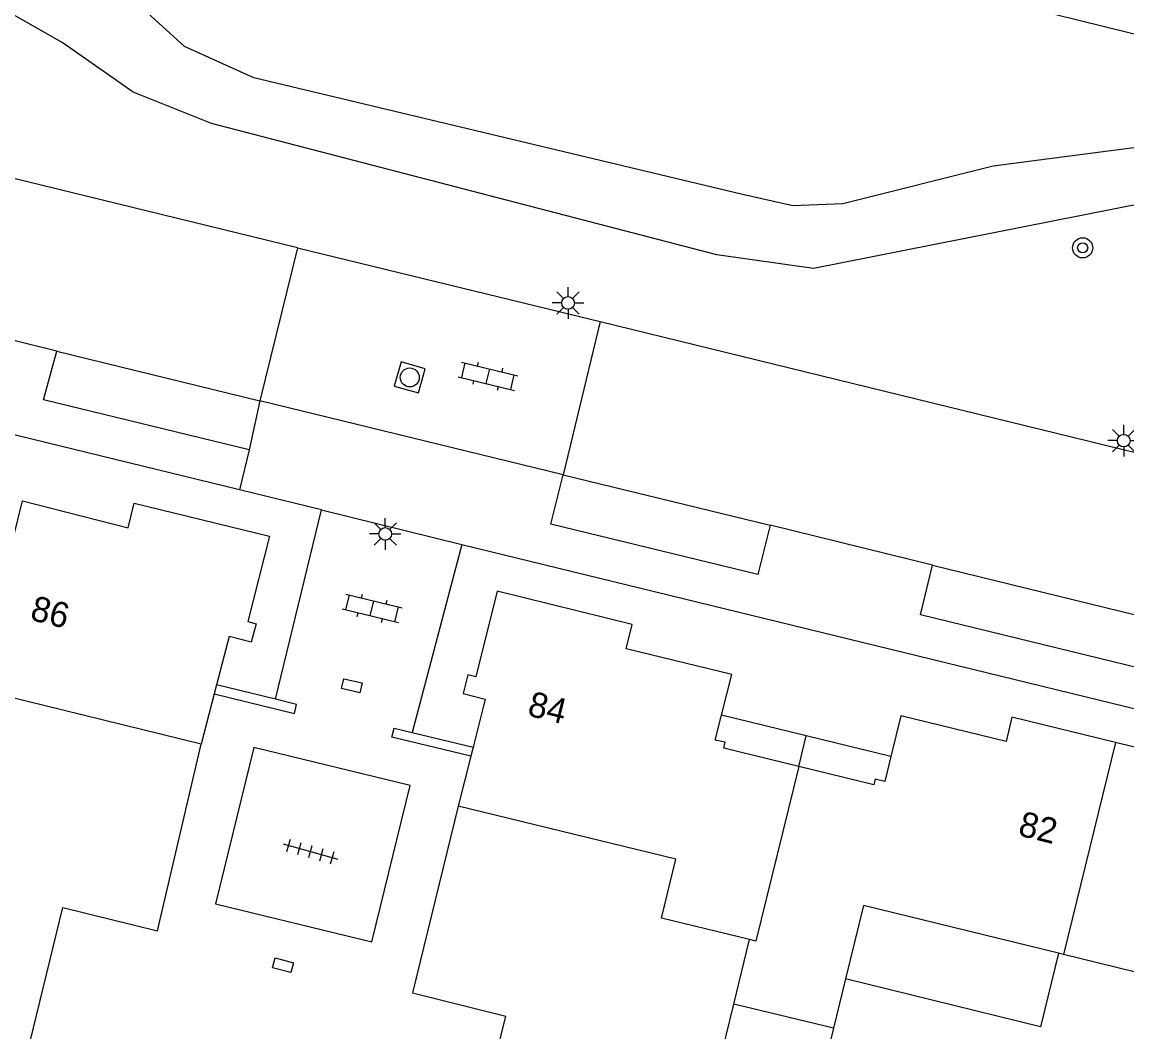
# Model space of a CAD drawing. Extents: x 125000 to 129004, y 397500 to 399008.
# Drawn here: x 126393.13 to 126436.93, y 398628.24 to 398668.28 of the extents above; entities that cross this region are included whole.
import ezdxf

# ---------------------------------------------------------------- set-up
doc = ezdxf.new("R2010")
doc.units = 0
for name, color, linetype in [('gg-afsc-muur', 7, 'Continuous'), ('gg-anno-huisnummerreeks BGT', 7, 'Continuous'), ('gg-bbg-hoofdgebouw', 7, 'Continuous'), ('gg-bbg-luifel en loopbrug', 7, 'Continuous'), ('gg-bbg-tussenscheiding', 7, 'Continuous'), ('gg-knt-verharding', 7, 'Continuous'), ('gg-knt-verharding nz', 7, 'Continuous'), ('gg-kntw-bovenkant insteek waterloop', 7, 'Continuous'), ('gt-grn-groengrens', 7, 'Continuous'), ('gt-grn-weggrens', 7, 'Continuous'), ('gt-symb-boom', 7, 'Continuous'), ('gt-symb-klinker verharding', 7, 'Continuous'), ('gt-symb-kolk center center', 7, 'Continuous'), ('gt-symb-lichtmast', 7, 'Continuous'), ('gt-symb-rioolschacht', 7, 'Continuous'), ('gt-symb-tegel verharding', 7, 'Continuous')]:
    doc.layers.add(name, color=color, linetype=linetype)

# ---------------------------------------------------------------- blocks, each defined once
blk = doc.blocks.new('gt0-LMAST')
at = {"layer": 'gt-symb-lichtmast'}
for p, q in [((-0.182, 0.173), (-0.447, 0.438)), ((-0.005, 0.246), (-0.005, 0.621)), ((0.172, 0.173), (0.437, 0.438)), ((-0.255, -0.004), (-0.63, -0.004)), ((-0.182, -0.181), (-0.447, -0.446)), ((-0.005, -0.254), (-0.005, -0.629)), ((0.437, -0.446), (0.172, -0.181)), ((0.245, -0.004), (0.62, -0.004))]:
    blk.add_line(p, q, dxfattribs=at)
blk.add_circle((-0.005, -0.004), 0.25, dxfattribs=at)
blk = doc.blocks.new('gt0-RS')
at = {"layer": 'gt-symb-rioolschacht'}
blk.add_lwpolyline([(-0.5, -0.5), (0.5, -0.5), (0.5, 0.5), (-0.5, 0.5)], close=True, dxfattribs=at)
blk.add_circle((0, 0), 0.375, dxfattribs=at)
blk = doc.blocks.new('gt0-KL1')
at = {"layer": 'gt-symb-klinker verharding'}
for p, q in [((-0.5, 0.3), (-0.5, 0.45)), ((0.5, 0.3), (0.5, 0.45)), ((-1.15, 0.3), (1.15, 0.3)), ((-1, -0.3), (-1, 0.3)), ((0, -0.3), (0, 0.3)), ((1, -0.3), (1, 0.3)), ((-1.15, -0.3), (1.15, -0.3)), ((-0.5, -0.45), (-0.5, -0.3)), ((0.5, -0.45), (0.5, -0.3))]:
    blk.add_line(p, q, dxfattribs=at)
blk = doc.blocks.new('gt0-KOLKCC')
at = {"layer": 'gt-symb-kolk center center'}
blk.add_lwpolyline([(-0.375, 0.2), (0.375, 0.2), (0.375, -0.2), (-0.375, -0.2)], close=True, dxfattribs=at)
blk = doc.blocks.new('gt0-TEG1')
at = {"layer": 'gt-symb-tegel verharding'}
for p, q in [((-1.125, 0), (1.125, 0)), ((-0.9, -0.25), (-0.9, 0.25)), ((-0.45, -0.25), (-0.45, 0.25)), ((0, -0.25), (0, 0.25)), ((0.45, -0.25), (0.45, 0.25)), ((0.9, -0.25), (0.9, 0.25))]:
    blk.add_line(p, q, dxfattribs=at)
blk = doc.blocks.new('gt0-BOOM')
at = {"layer": 'gt-symb-boom'}
for radius in [0.4, 0.2]:
    blk.add_circle((0, 0), radius, dxfattribs=at)

msp = doc.modelspace()

# ---------------------------------------------------------------- linework, layer by layer
at = {"layer": 'gg-afsc-muur'}
for p, q in [((126403.168, 398641.436), (126400.839, 398642.01)), ((126408.587, 398640.115), (126411.006, 398639.529)), ((126410.18, 398620.288), (126412.302, 398628.87))]:
    msp.add_line(p, q, dxfattribs=at)
for points in [[(126400.747, 398641.652), (126403.924, 398640.869), (126404.009, 398641.229), (126403.168, 398641.436)], [(126410.916, 398639.17), (126407.788, 398639.927), (126407.883, 398640.285), (126408.587, 398640.115)], [(126392.667, 398624.659), (126394.743, 398633.172), (126398.49, 398632.245), (126400.229, 398639.654)], [(126410.422, 398637.191), (126408.61, 398629.786), (126412.302, 398628.87)]]:
    msp.add_lwpolyline(points, dxfattribs=at)
at = {"layer": 'gg-bbg-hoofdgebouw'}
for p, q in [((126400.839, 398642.01), (126400.747, 398641.652)), ((126400.747, 398641.652), (126400.229, 398639.654)), ((126411.006, 398639.529), (126410.916, 398639.17)), ((126410.916, 398639.17), (126410.422, 398637.191)), ((126421.347, 398629.349), (126421.97, 398631.906)), ((126434.415, 398631.311), (126434.221, 398631.359)), ((126442.34, 398629.366), (126434.415, 398631.311)), ((126425.774, 398630.342), (126425.297, 398628.397)), ((126425.297, 398628.397), (126421.347, 398629.349))]:
    msp.add_line(p, q, dxfattribs=at)
for points in [[(126392.767, 398647.744), (126393.15, 398649.303), (126397.339, 398648.234), (126397.576, 398649.205), (126402.937, 398647.896), (126402.08, 398644.514), (126402.402, 398644.428), (126402.206, 398643.694), (126401.336, 398643.927), (126400.839, 398642.01)], [(126411.964, 398645.717), (126411.116, 398642.323), (126410.796, 398642.403), (126410.61, 398641.656), (126411.483, 398641.438), (126411.006, 398639.529)], [(126420.858, 398640.803), (126421.27, 398642.408), (126417.07, 398643.427), (126417.309, 398644.397), (126411.964, 398645.717)], [(126400.229, 398639.654), (126391.61, 398641.764), (126389.827, 398634.348), (126386.161, 398635.248)], [(126423.918, 398638.762), (126420.946, 398639.49), (126420.995, 398639.725), (126420.602, 398639.807), (126420.858, 398640.803)], [(126436.472, 398639.72), (126432.372, 398640.724), (126432.135, 398639.756), (126427.963, 398640.778), (126427.569, 398639.169)], [(126444.168, 398635.099), (126444.57, 398636.708), (126440.372, 398637.718), (126440.572, 398638.715), (126436.472, 398639.72)], [(126427.569, 398639.169), (126427.325, 398638.174), (126426.947, 398638.266), (126426.89, 398638.034), (126423.918, 398638.762)], [(126421.97, 398631.906), (126418.473, 398632.758), (126419.042, 398635.091), (126410.422, 398637.191)], [(126434.221, 398631.359), (126426.489, 398633.255), (126425.774, 398630.342)]]:
    msp.add_lwpolyline(points, dxfattribs=at)
at = {"layer": 'gg-bbg-luifel en loopbrug'}
for p, q in [((126424.216, 398639.986), (126420.858, 398640.803)), ((126423.918, 398638.762), (126424.216, 398639.986)), ((126427.569, 398639.169), (126424.216, 398639.986))]:
    msp.add_line(p, q, dxfattribs=at)
for points in [[(126434.221, 398631.359), (126433.506, 398628.445), (126425.774, 398630.342)], [(126425.297, 398628.397), (126424.669, 398625.836), (126420.723, 398626.804), (126421.347, 398629.349)]]:
    msp.add_lwpolyline(points, dxfattribs=at)
at = {"layer": 'gg-bbg-tussenscheiding'}
msp.add_line((126436.472, 398639.72), (126434.415, 398631.311), dxfattribs=at)
msp.add_lwpolyline([(126423.918, 398638.762), (126422.223, 398631.844), (126421.97, 398631.906)], dxfattribs=at)
at = {"layer": 'gg-knt-verharding'}
for p, q in [((126404.05, 398659.327), (126267.231, 398692.82)), ((126404.05, 398659.327), (126402.547, 398653.264)), ((126404.05, 398659.327), (126416.046, 398656.412)), ((126394.504, 398655.235), (126388.047, 398656.822)), ((126416.046, 398656.412), (126414.579, 398650.325)), ((126416.046, 398656.412), (126456.368, 398646.549)), ((126402.547, 398653.264), (126402.129, 398651.316)), ((126414.579, 398650.325), (126402.547, 398653.264)), ((126405.004, 398648.941), (126401.744, 398649.736)), ((126403.168, 398641.436), (126405.004, 398648.941)), ((126405.004, 398648.941), (126410.563, 398647.575)), ((126429.216, 398646.754), (126422.785, 398648.335)), ((126410.563, 398647.575), (126408.587, 398640.115))]:
    msp.add_line(p, q, dxfattribs=at)
for points in [[(126401.744, 398649.736), (126370.487, 398657.358), (126323.892, 398668.809), (126286.162, 398678.033), (126285.184, 398678.288)], [(126402.129, 398651.316), (126393.983, 398653.305), (126394.504, 398655.235)], [(126422.785, 398648.335), (126422.294, 398646.378), (126414.091, 398648.375), (126414.579, 398650.325)], [(126410.563, 398647.575), (126475.229, 398631.783), (126528.498, 398618.73), (126646.676, 398589.816)], [(126446.091, 398642.609), (126445.647, 398640.65), (126428.742, 398644.785), (126429.216, 398646.754)], [(126406.996, 398631.816), (126408.517, 398638.007), (126402.319, 398639.519), (126400.79, 398633.322), (126406.996, 398631.816)]]:
    msp.add_lwpolyline(points, dxfattribs=at)
at = {"layer": 'gg-knt-verharding nz'}
for p, q in [((126394.504, 398655.235), (126402.547, 398653.264)), ((126414.579, 398650.325), (126422.785, 398648.335)), ((126429.216, 398646.754), (126446.091, 398642.609))]:
    msp.add_line(p, q, dxfattribs=at)
at = {"layer": 'gg-kntw-bovenkant insteek waterloop'}
msp.add_lwpolyline([(126416.244, 398672.929), (126432.133, 398669.072), (126510.587, 398649.723), (126549.24, 398640.255), (126624.257, 398621.922), (126650.985, 398615.296), (126659.461, 398613.222)], dxfattribs=at)
at = {"layer": 'gt-grn-groengrens'}
for points in [[(126456.368, 398646.549), (126457.531, 398651.299), (126457.312, 398653.173), (126452.206, 398660.166), (126446.763, 398661.408), (126437.604, 398661.105), (126424.5, 398658.511), (126420.672, 398659.056), (126400.635, 398664.263), (126397.533, 398665.499), (126394.722, 398667.479), (126391.948, 398669.051), (126389.419, 398669.199), (126381.253, 398668.904), (126374.631, 398669.08), (126362.044, 398672.033), (126357.278, 398673.586), (126353.232, 398676.669), (126350.519, 398680.566), (126348.113, 398683.897), (126344.654, 398685.265), (126322.066, 398690.378), (126318.659, 398690.426), (126314.271, 398689.815)], [(126686.829, 398601.086), (126686.71, 398601.196), (126682.165, 398605.078), (126680.031, 398606.481), (126677.259, 398607.61), (126447.199, 398663.906), (126441.156, 398663.817), (126431.621, 398662.572), (126425.661, 398661.08), (126423.684, 398661.001), (126421.639, 398661.453), (126402.312, 398666.071), (126399.561, 398667.314), (126397.23, 398669.459), (126394.183, 398671.219), (126391.793, 398671.729), (126378.802, 398671.135), (126378.013, 398671.207)]]:
    msp.add_lwpolyline(points, dxfattribs=at)
at = {"layer": 'gt-grn-weggrens'}
msp.add_line((126402.129, 398651.316), (126401.744, 398649.736), dxfattribs=at)

# ---------------------------------------------------------------- block references
at = {"layer": 'gt-symb-boom'}
msp.add_blockref('gt0-BOOM', (126435.173, 398659.331), dxfattribs=at)
at = {"layer": 'gt-symb-klinker verharding', "rotation": -13.772145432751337}
for p in [(126411.599, 398654.239), (126407.004, 398645.038)]:
    msp.add_blockref('gt0-KL1', p, dxfattribs=at)
at = {"layer": 'gt-symb-kolk center center'}
for p, rotation in [((126406.198, 398641.968), 167.11702052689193), ((126403.472, 398630.888), 165.57446822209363)]:
    msp.add_blockref('gt0-KOLKCC', p, dxfattribs=dict(at, rotation=rotation))
at = {"layer": 'gt-symb-lichtmast'}
for p in [(126414.778, 398657.15), (126436.807, 398651.69), (126407.528, 398647.991)]:
    msp.add_blockref('gt0-LMAST', p, dxfattribs=at)
at = {"layer": 'gt-symb-rioolschacht', "rotation": -15.843082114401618}
msp.add_blockref('gt0-RS', (126408.496, 398654.194), dxfattribs=at)
at = {"layer": 'gt-symb-tegel verharding', "rotation": -15.787947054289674}
msp.add_blockref('gt0-TEG1', (126404.561, 398635.395), dxfattribs=at)

# ---------------------------------------------------------------- texts
at = {"layer": 'gg-anno-huisnummerreeks BGT'}
for s, rotation, p in [('86', 345.7, (126393.404, 398644.593)), ('84', 346.1, (126413.122, 398640.797)), ('82', 346.2, (126432.573, 398636.042))]:
    msp.add_text(s, height=1, rotation=rotation, dxfattribs=at).set_placement(p)

doc.saveas('drawing.dxf')
